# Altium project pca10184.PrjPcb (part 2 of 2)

## Sheet pca10184_connectors.SchDoc: =ProductName + ' - Connectors'
size A3; Organization: Nordic Semiconductor; DocumentNumber: 8; Revision: 0.3.4; SheetNumber: 8; SheetTotal: 9; Author: GETR; CompanyName: Nordic Semiconductor; DrawnBy: GETR; DocumentSize: A3
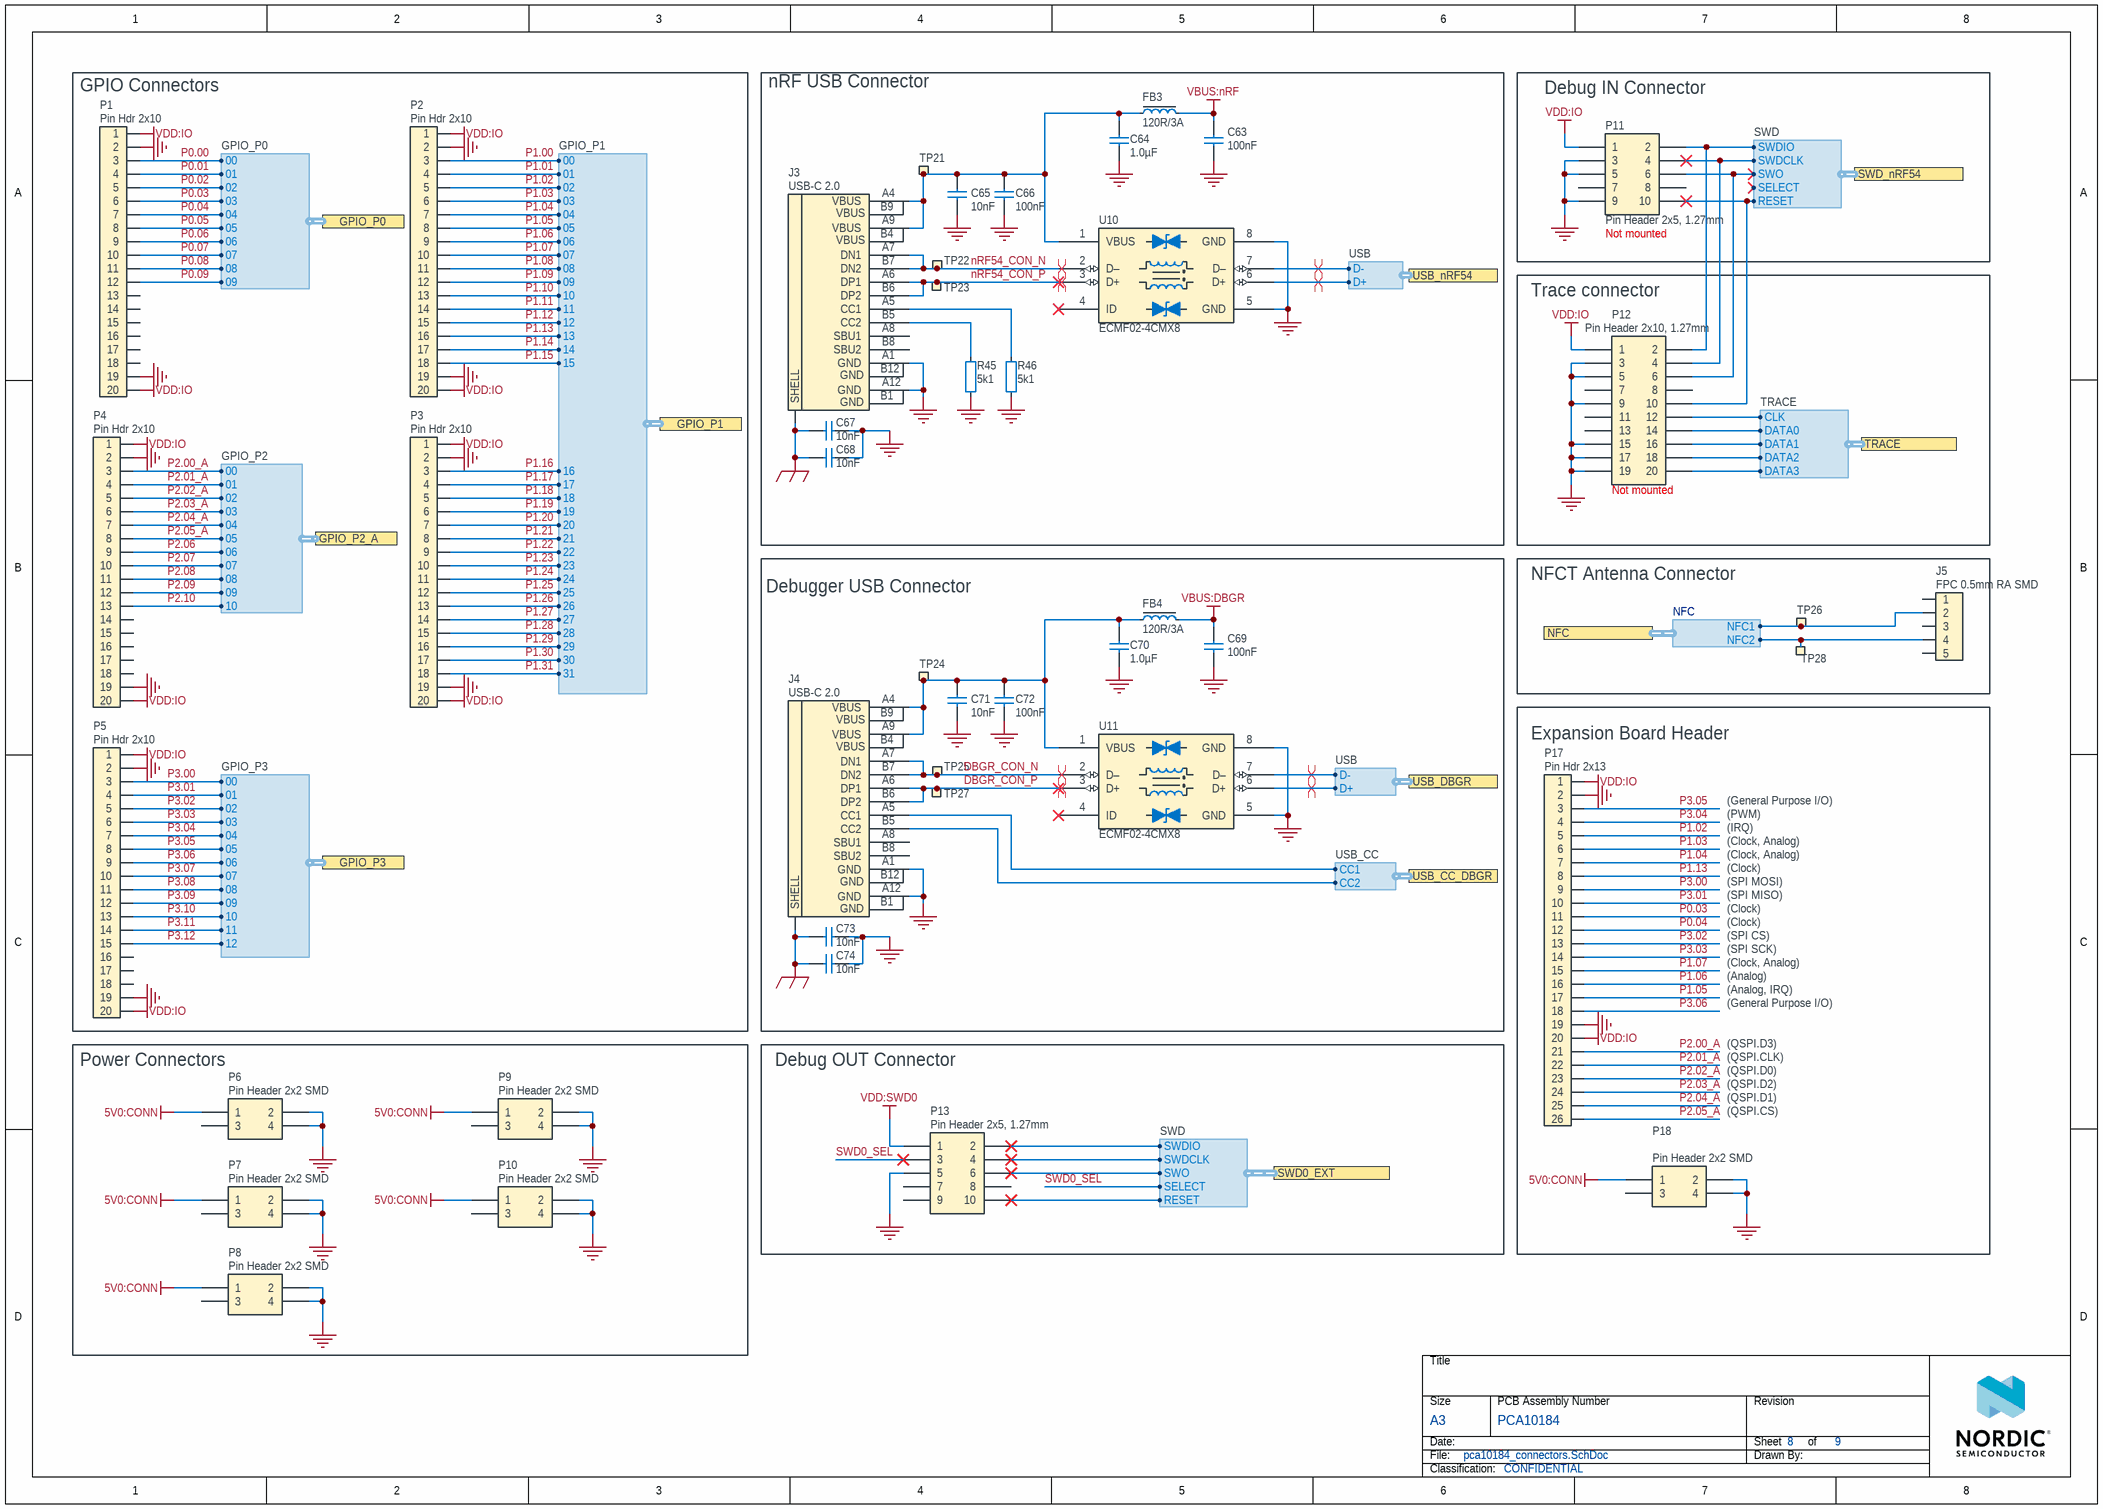
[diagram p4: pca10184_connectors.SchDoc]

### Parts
C63  100nF  [CAPC0603X03L_C]
C64  1.0µF  [CAPC1005X04L]
C65  10nF  [CAPC0603X03L_C]
C66  100nF  [CAPC0603X03L_C]
C67  10nF  [CAPC1005X04L]
C68  10nF  [CAPC1005X04L]
C69  100nF  [CAPC0603X03L_C]
C70  1.0µF  [CAPC1005X04L]
C71  10nF  [CAPC0603X03L_C]
C72  100nF  [CAPC0603X03L_C]
C73  10nF  [CAPC1005X04L]
C74  10nF  [CAPC1005X04L]
FB3  120R/3A  [INDC1608X06L]
FB4  120R/3A  [INDC1608X06L]
J3  USB-C 2.0  [SD-80259-001]
J4  USB-C 2.0  [SD-80259-001]
J5  FPC 0.5mm RA SMD  [FPC_05P-0.5mm-RA-SMD]
P1  Pin Hdr 2x10  [HDR_2x10-SMD]
P2  Pin Hdr 2x10  [HDR_2x10-SMD]
P3  Pin Hdr 2x10  [HDR_2x10-SMD]
P4  Pin Hdr 2x10  [HDR_2x10-SMD]
P5  Pin Hdr 2x10  [HDR_2x10-SMD]
P6  Pin Header 2x2 SMD  [HDR_2x2-SMD]
P7  Pin Header 2x2 SMD  [HDR_2x2-SMD]
P8  Pin Header 2x2 SMD  [HDR_2x2-SMD]
P9  Pin Header 2x2 SMD  [HDR_2x2-SMD]
P10  Pin Header 2x2 SMD  [HDR_2x2-SMD]
P11  Pin Header 2x5, 1.27mm  Assembly: Not mounted  [HDR_2x5-SMD-1.27mm-K]
P12  Pin Header 2x10, 1.27mm  Assembly: Not mounted  [HDR_2x10-SMD-1.27mm-NC]
P13  Pin Header 2x5, 1.27mm  [HDR_2x5-SMD-1.27mm-K]
P17  Pin Hdr 2x13  [HDR_2x13-SMD]
P18  Pin Header 2x2 SMD  [HDR_2x2-SMD]
R45  5k1  [RESC0603X03L_C]
R46  5k1  [RESC0603X03L_C]
TP21  Ø1.5mm,SMD  [TP_SMD_D1.5mm]  (value not drawn)  (no BOM)
TP22  Ø1.5mm,SMD  [TP_SMD_D1.5mm]  (value not drawn)  (no BOM)
TP23  Ø1.5mm,SMD  [TP_SMD_D1.5mm]  (value not drawn)  (no BOM)
TP24  Ø1.5mm,SMD  [TP_SMD_D1.5mm]  (value not drawn)  (no BOM)
TP25  Ø1.5mm,SMD  [TP_SMD_D1.5mm]  (value not drawn)  (no BOM)
TP26  Ø1.5mm,SMD  [TP_SMD_D1.5mm]  (value not drawn)  (no BOM)
TP27  Ø1.5mm,SMD  [TP_SMD_D1.5mm]  (value not drawn)  (no BOM)
TP28  Ø1.5mm,SMD  [TP_SMD_D1.5mm]  (value not drawn)  (no BOM)
U10  ECMF02-4CMX8  [UFDFN50P120X250X55-8N]
U11  ECMF02-4CMX8  [UFDFN50P120X250X55-8N]

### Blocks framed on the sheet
GPIO Connectors: P1-P5
nRF USB Connector: C63-C68 FB3 J3 R45 R46 TP21-TP23 U10
Debug IN Connector: P11
Trace connector: P12
Debugger USB Connector: C69-C74 FB4 J4 TP24 TP25 TP27 U11
NFCT Antenna Connector: J5 TP26 TP28
Expansion Board Header: P17 P18
Power Connectors: P6-P10
Debug OUT Connector: P13

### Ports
GPIO_P0 (harness GPIO_P0), GPIO_P1 (harness GPIO_P1), GPIO_P2_A (harness GPIO_P2), GPIO_P3 (harness GPIO_P3), NFC (harness NFC), SWD0_EXT (harness SWD), SWD_nRF54 (harness SWD), TRACE (harness TRACE), USB_CC_DBGR (harness USB_CC), USB_DBGR (harness USB), USB_nRF54 (harness USB)

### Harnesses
GPIO_P0: 00, 01, 02, 03, 04, 05, 06, 07, 08, 09
GPIO_P1: 00, 01, 02, 03, 04, 05, 06, 07, 08, 09, 10, 11, 12, 13, 14, 15, 16, 17, 18, 19, 20, 21, 22, 23, 24, 25, 26, 27, 28, 29, 30, 31
GPIO_P3: 00, 01, 02, 03, 04, 05, 06, 07, 08, 09, 10, 11, 12
SWD: SWDIO, SWDCLK, SWO, RESET, SELECT
USB: D+, D-
USB_CC: CC2, CC1
NFC: NFC2, NFC1
TRACE: CLK, DATA0, DATA1, DATA3, DATA2
GPIO_P2: 00, 01, 02, 03, 04, 05, 06, 07, 08, 09, 10

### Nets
5V0:CONN: P6.1 P7.1 P8.1 P9.1 P10.1 P18.1
GND: C63.1 C64.1 C65.1 C66.1 C67.2 C68.2 C69.1 C70.1 C71.1 C72.1 C73.2 C74.2 J3.A1(GND) J3.A12(GND) J4.A1(GND) J4.A12(GND) P1.2 P1.19 P2.2 P2.19 P3.2 P3.19 P4.2 P4.19 P5.2 P5.19 P6.2 P6.4 P7.2 P7.4 P8.2 P8.4 P9.2 P9.4 P10.2 P10.4 P11.3 P11.5 P11.9 P12.3 P12.5 P12.9 P12.15 P12.17 P12.19 P13.5 P17.2 P17.19 P18.2 P18.4 R45.1 R46.1 U10.5(GND) U10.8(GND) U11.5(GND) U11.8(GND)
Shield: C67.1 C68.1 C73.1 C74.1 J3.SHLD(SHELL) J4.SHLD(SHELL)
VBUS:DBGR: C69.2 FB4.2
VBUS:nRF: C63.2 FB3.2
VDD:IO: P1.1 P1.20 P2.1 P2.20 P3.1 P3.20 P4.1 P4.20 P5.1 P5.20 P11.1 P12.1 P17.1 P17.20
VDD:SWD0: P13.1
DBGR_CON_N: J4.A7(DN1) J4.B7(DN2) TP25.1 U11.2(D–)
DBGR_CON_P: J4.A6(DP1) J4.B6(DP2) TP27.1 U11.3(D+)
DBGR_N: U11.7(D–) ; port USB_DBGR.D-
DBGR_P: U11.6(D+) ; port USB_DBGR.D+
NFC1_N: J5.2 TP26.1 ; port NFC.NFC1
NFC2_P: J5.4 TP28.1 ; port NFC.NFC2
nRF54_CON_N: J3.A7(DN1) J3.B7(DN2) TP22.1 U10.2(D–)
nRF54_CON_P: J3.A6(DP1) J3.B6(DP2) TP23.1 U10.3(D+)
nRF54_RESET: P11.10 P12.10 ; port SWD_nRF54.RESET
P0.00: P1.3 ; port GPIO_P0.00
P0.01: P1.4 ; port GPIO_P0.01
P0.02: P1.5 ; port GPIO_P0.02
P0.03: P1.6 P17.11 ; port GPIO_P0.03
P0.04: P1.7 P17.12 ; port GPIO_P0.04
P0.05: P1.8 ; port GPIO_P0.05
P0.06: P1.9 ; port GPIO_P0.06
P0.07: P1.10 ; port GPIO_P0.07
P0.08: P1.11 ; port GPIO_P0.08
P0.09: P1.12 ; port GPIO_P0.09
P1.00: P2.3 ; port GPIO_P1.00
P1.01: P2.4 ; port GPIO_P1.01
P1.02: P2.5 P17.5 ; port GPIO_P1.02
P1.03: P2.6 P17.6 ; port GPIO_P1.03
P1.04: P2.7 P17.7 ; port GPIO_P1.04
P1.05: P2.8 P17.17 ; port GPIO_P1.05
P1.06: P2.9 P17.16 ; port GPIO_P1.06
P1.07: P2.10 P17.15 ; port GPIO_P1.07
P1.08: P2.11 ; port GPIO_P1.08
P1.09: P2.12 ; port GPIO_P1.09
P1.10: P2.13 ; port GPIO_P1.10
P1.11: P2.14 ; port GPIO_P1.11
P1.12: P2.15 ; port GPIO_P1.12
P1.13: P2.16 P17.8 ; port GPIO_P1.13
P1.14: P2.17 ; port GPIO_P1.14
P1.15: P2.18 ; port GPIO_P1.15
P1.16: P3.3 ; port GPIO_P1.16
P1.17: P3.4 ; port GPIO_P1.17
P1.18: P3.5 ; port GPIO_P1.18
P1.19: P3.6 ; port GPIO_P1.19
P1.20: P3.7 ; port GPIO_P1.20
P1.21: P3.8 ; port GPIO_P1.21
P1.22: P3.9 ; port GPIO_P1.22
P1.23: P3.10 ; port GPIO_P1.23
P1.24: P3.11 ; port GPIO_P1.24
P1.25: P3.12 ; port GPIO_P1.25
P1.26: P3.13 ; port GPIO_P1.26
P1.27: P3.14 ; port GPIO_P1.27
P1.28: P3.15 ; port GPIO_P1.28
P1.29: P3.16 ; port GPIO_P1.29
P1.30: P3.17 ; port GPIO_P1.30
P1.31: P3.18 ; port GPIO_P1.31
P2.00_A: P4.3 P17.21 ; port GPIO_P2_A.00
P2.01_A: P4.4 P17.22 ; port GPIO_P2_A.01
P2.02_A: P4.5 P17.23 ; port GPIO_P2_A.02
P2.03_A: P4.6 P17.24 ; port GPIO_P2_A.03
P2.04_A: P4.7 P17.25 ; port GPIO_P2_A.04
P2.05_A: P4.8 P17.26 ; port GPIO_P2_A.05
P2.06: P4.9 P12.12 ; port TRACE.CLK, port GPIO_P2_A.06
P2.07: P4.10 P11.6 P12.6 P12.14 ; port SWD_nRF54.SWO, port TRACE.DATA0, port GPIO_P2_A.07
P2.08: P4.11 P12.16 ; port TRACE.DATA1, port GPIO_P2_A.08
P2.09: P4.12 P12.18 ; port TRACE.DATA2, port GPIO_P2_A.09
P2.10: P4.13 P12.20 ; port TRACE.DATA3, port GPIO_P2_A.10
P3.00: P5.3 P17.9 ; port GPIO_P3.00
P3.01: P5.4 P17.10 ; port GPIO_P3.01
P3.02: P5.5 P17.13 ; port GPIO_P3.02
P3.03: P5.6 P17.14 ; port GPIO_P3.03
P3.04: P5.7 P17.4 ; port GPIO_P3.04
P3.05: P5.8 P17.3 ; port GPIO_P3.05
P3.06: P5.9 P17.18 ; port GPIO_P3.06
P3.07: P5.10 ; port GPIO_P3.07
P3.08: P5.11 ; port GPIO_P3.08
P3.09: P5.12 ; port GPIO_P3.09
P3.10: P5.13 ; port GPIO_P3.10
P3.11: P5.14 ; port GPIO_P3.11
P3.12: P5.15 ; port GPIO_P3.12
SWD0_CLK_EXT: P13.6 ; port SWD0_EXT.SWO
SWD0_IO_EXT: P13.10 ; port SWD0_EXT.RESET
SWD0_RESET_EXT: P13.2 ; port SWD0_EXT.SWDIO
SWD0_SEL: P13.3 ; port SWD0_EXT.SELECT
SWD0_SWO_EXT: P13.4 ; port SWD0_EXT.SWDCLK
SWDCLK: P11.4 P12.4 ; port SWD_nRF54.SWDCLK
SWDIO: P11.2 P12.2 ; port SWD_nRF54.SWDIO
USB_nRF54_D+: U10.6(D+) ; port USB_nRF54.D+
USB_nRF54_D-: U10.7(D–) ; port USB_nRF54.D-
NetC64_2: C64.2 C65.2 C66.2 FB3.1 J3.A4(VBUS) J3.A9(VBUS) TP21.1 U10.1(VBUS)
NetC70_2: C70.2 C71.2 C72.2 FB4.1 J4.A4(VBUS) J4.A9(VBUS) TP24.1 U11.1(VBUS)
NetJ3_A5: J3.A5(CC1) R46.2
NetJ3_B5: J3.B5(CC2) R45.2
NetJ4_A5: J4.A5(CC1) ; port USB_CC_DBGR.CC1
NetJ4_B5: J4.B5(CC2) ; port USB_CC_DBGR.CC2

Not connected (* = marked no-connect by the designer): J3 A8(SBU1) B8(SBU2); J4 A8(SBU1) B8(SBU2); J5 1 3 5; P1 13 14 15 16 17 18; P4 14 15 16 17 18; P5 16 17 18; P6 3; P7 3; P8 3; P9 3; P10 3; P11 7 8; P12 7 8 11 13; P13 7 8 9; P18 3; U10 4(ID)*; U11 4(ID)*

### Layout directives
differential pair; differential pair class nRF54; net class USB: DBGR_CON_N, DBGR_CON_P, nRF54_CON_N, nRF54_CON_P
differential pair; differential pair class IMCU; net class USB: DBGR_N, DBGR_P, USB_nRF54_D+, USB_nRF54_D-

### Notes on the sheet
- (Clock, Analog)
- (IRQ)
- (PWM)
- (General Purpose I/O)
- (Clock)
- (SPI MOSI)
- (SPI MISO)
- (Analog)
- (Analog, IRQ)
- (SPI SCK)
- (SPI CS)
- (QSPI.D3)
- (QSPI.D2)
- (QSPI.D0)
- (QSPI.D1)
- (QSPI.CS)
- (QSPI.CLK)

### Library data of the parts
C63 C66 C69 C72 = C0201-100n: Capacitor, X5R, ±10%, 100nF, 16V; Manufacturer: N.A.; Part number IPS: 00000001248, 00000002505; Part number Norautron: 262071862; Part number NEMS: 100200078; Pad Count: 2; Component Status: Active
C64 C70 = C0402-1µ0-16V-X5R: Capacitor, Ceramic, X5R, ±10%, 16V; Manufacturer: Murata; Manufacturer Part Number: GRT155R61C105KE01D; Part number NEMS: 100200452; Artikkelnr Noca: N.A.; Pad Count: 2; Component Status: Active
C65 C71 = C0201-10n: Capacitor, X7R, ±10%, 10nF, 10V; Manufacturer: N.A.; Part number IPS: 00000003480; Part number Norautron: 26621779; Part number NEMS: 100200067; Pad Count: 2; Component Status: Active
C67 C68 C73 C74 = C0402-10n: Capacitor, X7R, ±10%; Manufacturer: N.A.; Part number IPS: 00000007784; Part number NEMS: 100200173; Component Status: Active; Pad Count: 2; Note: 16V; Artikkelnr Noca: 20039166
FB3 FB4 = FB0603-120R@100MHz-3000mA: Ferrite Bead, 120 Ohm @ 100MHz, 3000mA, 30 mOhm Max; Manufacturer: Murata; Manufacturer Part Number: BLM18KG121TN1D; Part number NEMS: 100300103; Component Status: Active; Pad Count: 2; Note: Chip EMIFIL Inductor Type Chip Ferrite Bead; Artikkelnr Noca: N.A.
J3 J4 = 80259-1021: USB-C Receptacle, 16 Pin, USB 2.0; Manufacturer: Bellweather Electronic Corp.; Part number NEMS: 100500830; Component Status: Active; Pad Count: 16; Note: N.A.; System: Connector
J5 = FPC_05P-0.5mm-RA-SMD: 0.5mm FPC, 5P,Right Angle SMT,Double Contact,H=1.2mm,White, Tin plated; Manufacturer: WCON; Manufacturer Part Number: 5141-05RZDNWR03; Part number NEMS: 100500528; Note: (Replaced 5141-05RZDNWR02); Artikkelnr Noca: N.A.; Pad Count: 7; Component Status: Active; System: Connector
P1-P5 = Pin Header 2x10 SMD, 2.54mm: Pin Header 2x10, 2.54mm (100mil) SMD; Manufacturer: WCON; Manufacturer Part Number: 1125-1210S0M116CR09; Part number NEMS: 100500738; Pad Count: 20; Artikkelnr Noca: N.A.; Component Status: Active; System: Connector
P6-P10 P18 = Pin Header 2x2 SMD: Pin Header 2x2, SMD, 2.54mm (100mil); Manufacturer: WCON; Manufacturer Part Number: 1125-1202S0M116CR03; Part number NEMS: 100500770; Component Status: Active; Pad Count: 4; Note: N.A.; System: Connector
P11 P13 = Pin Header 2x5 SMD, 1.27mm, KS: Pin Header 2x5, 1.27mm (50mil), SMD, Keying Shroud; Manufacturer: WCON; Manufacturer Part Number: 3132-10MS0BK00R5; Part number NEMS: 100500261; Note: (Replaced 3132-10MS0BK00R1); Artikkelnr Noca: N.A.; Pad Count: 10; Component Status: Active; System: Connector
P12 = Pin Header 2x10 SMD, 1.27mm, KS, N.C.: Pin Header 2x10, 1.27mm (50mil), SMD, Keying Shroud; Manufacturer: WCON; Manufacturer Part Number: 3132-20MS0BK00R1; Part number NEMS: 100500279; Note: N.A.; Pad Count: 20; Component Status: Active; System: Connector
P17 = Pin Header 2x13 SMD, 2.54mm: Pin Header 2x13, 2.54mm (100mil) SMD; Manufacturer: WCON; Manufacturer Part Number: 1125-1213S0M116CR09; Part number NEMS: 100500908; Component Status: Active; Pad Count: 26; Artikkelnr Noca: N.A.; System: Connector
R45 R46 = R0201-5k1: Resistor, ±1%, 0.05W; Manufacturer: N.A.; Part number Norautron: 26192285; Part number NEMS: 100100565; Pad Count: 2; Note: Chip Res 1%; Component Status: Active
TP21-TP28 = TP_SMD_Ø1.5MM: 1.5mm circular SMD testpad; Manufacturer: Nordic Semiconductor; Manufacturer Part Number: N.A.; Part number NEMS: 100500477; Pad Count: 1; Component Status: Active
U10 U11 = ECMF02-4CMX8: 2 Line Common mode filter with ESD protection for USB 2.0 interface, DCRmax = 4Ohm, -40°C ~ 125°C; Manufacturer: STMicroelectronics; Part number NEMS: 100800034; Component Status: Active; Pad Count: 8; Note: N.A.

## Sheet pca10184_mechanical.SchDoc: =ProductName + ' - Mechanical'
size A4; Organization: Nordic Semiconductor; DocumentNumber: 9; Revision: 0.3.4; SheetNumber: 9; SheetTotal: 9; Author: GETR; CompanyName: Nordic Semiconductor; DrawnBy: GETR; DocumentSize: A4
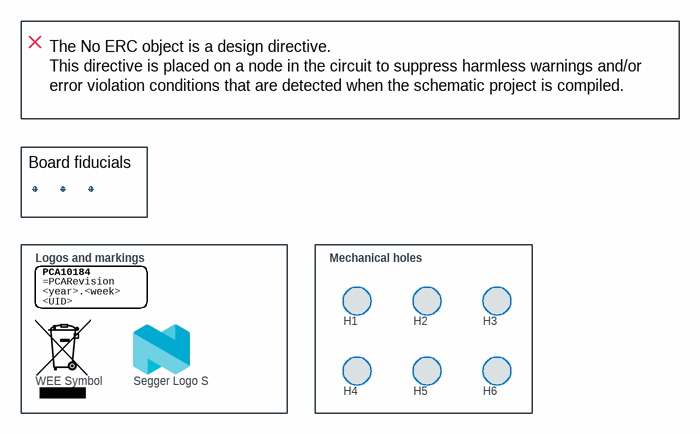
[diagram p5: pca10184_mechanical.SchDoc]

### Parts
Fid1  Fiducial mark  [Fiducial]  (value not drawn)
Fid2  Fiducial mark  [Fiducial]  (value not drawn)
Fid3  Fiducial mark  [Fiducial]  (value not drawn)
H1  MountingHole_NPTH  [MountingHole_3.2_M3]  (value not drawn)  (no BOM)
H2  MountingHole_NPTH  [MountingHole_3.2_M3]  (value not drawn)  (no BOM)
H3  MountingHole_NPTH  [MountingHole_3.2_M3]  (value not drawn)  (no BOM)
H4  MountingHole_NPTH  [MountingHole_3.2_M3]  (value not drawn)  (no BOM)
H5  MountingHole_NPTH  [MountingHole_3.2_M3]  (value not drawn)  (no BOM)
H6  MountingHole_NPTH  [MountingHole_3.2_M3]  (value not drawn)  (no BOM)
LABEL1  12x12mm  [LabelSilk_12x12]  (value not drawn)
LOGO1  WEE Symbol  [WEE_3x4.5mm]  (no BOM)
LOGO3  Segger Logo S  [SEGGER_LOGO_S]  (no BOM)

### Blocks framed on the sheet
Logos and markings: LABEL1 LOGO1 LOGO3
Mechanical holes: H1-H6

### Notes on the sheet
- The No ERC object is a design directive.
  This directive is placed on a node in the circuit to suppress harmless warnings and/or error violation conditions that are detected when the schematic project is compiled.
- Board fiducials

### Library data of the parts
Fid1-Fid3 = Fid-Mark: Manufacturer: N.A.; Part number NEMS: 100500073; Value: N.A.; Pad Count: 1; Component Status: Active; System: Connector
H1-H6 = MountingHole_3.2_M3: Mounting hole, 3.2mm, M3, no annular; Manufacturer: N.A.; Part number NEMS: 101200008; Rule: UNIONINDEX=0¦RULEKIND=Clearance¦NETSCOPE=DifferentNets¦LAYERKIND=SameLayer¦NAME=Schematic Clearance Constraint¦GAP=10mil¦GENERICCLEARANCE=10mil¦IGNOREPADTOPADCLEARANCEINFOOTPRINT=TRUE¦OBJECTCLEARANCES=ClearanceObj_Arc-ClearanceObj_Hole:0;ClearanceObj_Track-ClearanceObj_Hole:0;ClearanceObj_SMDPad-ClearanceObj_Hole:0;ClearanceObj_THPad-ClearanceObj_Hole:0;ClearanceObj_Via-ClearanceObj_Hole:0;ClearanceObj_Fill-ClearanceObj_Hole:0;ClearanceObj_Poly-ClearanceObj_Hole:0;ClearanceObj_Region-ClearanceObj_Hole:0;ClearanceObj_Text-ClearanceObj_Hole:0¦UNIT=Metric; Rule: UNIONINDEX=0¦RULEKIND=RoutingVias¦NETSCOPE=AnyNet¦LAYERKIND=SameLayer¦NAME=Schematic Routing Via Style¦HOLEWIDTH=0mil¦WIDTH=0mil¦VIASTYLE=Through Hole¦MINHOLEWIDTH=0mil¦MINWIDTH=0mil¦MAXHOLEWIDTH=78.7402mil¦MAXWIDTH=78.7402mil¦UNIT=Metric; Component Status: Active; Pad Count: 0
LABEL1 = Label_12x12: PCA version label, stick-on, 12x12mm; Manufacturer: Ellco Etikett; Manufacturer Part Number: A33512‐01; Part number NEMS: 101200028; Component Status: Active; Pad Count: 0; Note: N.A.
LOGO1 = WEEE Symbol 3x4.5mm: WEEE Directive symbol; Manufacturer: N.A.; Part number NEMS: 101100006; Component Status: Active; Pad Count: 0
LOGO3 = Segger Logo S: Segger logo, small size; Manufacturer: N.A.; Part number NEMS: 101100004; Component Status: Active; Pad Count: 0

## Sheet pca10184_misc.SchDoc: =ProductName + ' - Misc'
size A3; Author: GETR; CompanyName: Nordic Semiconductor; DrawnBy: GETR; DocumentNumber: 5; Revision: 0.3.4; SheetNumber: 5; SheetTotal: 9
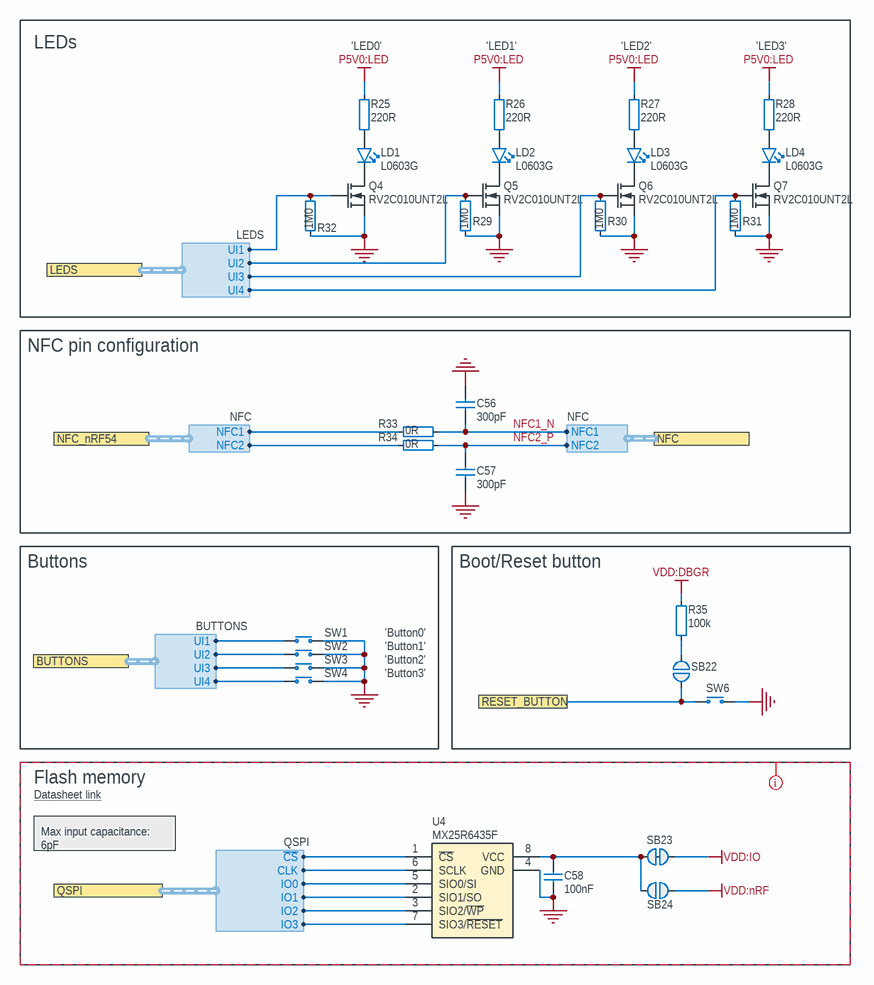
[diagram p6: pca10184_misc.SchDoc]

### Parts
C56  300pF  [CAPC1005X04L]
C57  300pF  [CAPC1005X04L]
C58  100nF  [CAPC0603X03L_C]
LD1  L0603G  [LED_0603_G]
LD2  L0603G  [LED_0603_G]
LD3  L0603G  [LED_0603_G]
LD4  L0603G  [LED_0603_G]
Q4  RV2C010UNT2L  [DFN65P100X40-3L]
Q5  RV2C010UNT2L  [DFN65P100X40-3L]
Q6  RV2C010UNT2L  [DFN65P100X40-3L]
Q7  RV2C010UNT2L  [DFN65P100X40-3L]
R25  220R  [RESC0603X03L_C]
R26  220R  [RESC0603X03L_C]
R27  220R  [RESC0603X03L_C]
R28  220R  [RESC0603X03L_C]
R29  1M0  [RESC0603X03L_C]
R30  1M0  [RESC0603X03L_C]
R31  1M0  [RESC0603X03L_C]
R32  1M0  [RESC0603X03L_C]
R33  0R  [RESC1005X04L]
R34  0R  [RESC1005X04L]
R35  100k  [RESC0603X03L_C]
SB22  Solderbridge  [Solderbridge]  (value not drawn)  (no BOM)
SB23  Solderbridge  [Solderbridge_Shorted]  (value not drawn)  (net tie, no BOM)
SB24  Solderbridge  [Solderbridge]  (value not drawn)  (no BOM)
SW1  PB SW  [Switch-PB-6.2x6.3mm-SMD]  (value not drawn)
SW2  PB SW  [Switch-PB-6.2x6.3mm-SMD]  (value not drawn)
SW3  PB SW  [Switch-PB-6.2x6.3mm-SMD]  (value not drawn)
SW4  PB SW  [Switch-PB-6.2x6.3mm-SMD]  (value not drawn)
SW6  PB SW  [Switch-PB-6.2x6.3mm-SMD]  (value not drawn)
U4  MX25R6435F  [SON127P600X80_HS-9N]

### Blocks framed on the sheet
LEDs: LD1-LD4 Q4-Q7 R25-R32
NFC pin configuration: C56 C57 R33 R34
Buttons: SW1-SW4
Boot/Reset button: R35 SB22 SW6
Flash memory: C58 SB23 SB24 U4

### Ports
BUTTONS (harness BUTTONS), LEDS (harness LEDS), NFC (harness NFC), NFC_nRF54 (harness NFC), QSPI (harness QSPI), RESET_BUTTON

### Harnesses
NFC: NFC2, NFC1
LEDS: UI2, UI1, UI3, UI4
QSPI: ~{CS}, IO0, CLK, IO1, IO2, IO3
BUTTONS: UI2, UI3, UI4, UI1

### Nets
GND: C56.2 C57.1 C58.2 Q4.2(S) Q5.2(S) Q6.2(S) Q7.2(S) R29.2 R30.2 R31.2 R32.2 SW1.1(N.O) SW2.1(N.O) SW3.1(N.O) SW4.1(N.O) SW6.1(N.O) U4.4(GND) U4.9(GND)
P5V0:LED: R25.2 R26.2 R27.2 R28.2
VDD:DBGR: R35.2
VDD:IO: SB23.1
VDD:nRF: SB24.1
NFC1_N: C56.1 R33.2 ; port NFC.NFC1
NFC2_P: C57.2 R34.2 ; port NFC.NFC2
NFC_N: R33.1 ; port NFC_nRF54.NFC1
NFC_P: R34.1 ; port NFC_nRF54.NFC2
P0.05: SW4.2(COM) ; port BUTTONS.UI4
P1.08: SW3.2(COM) ; port BUTTONS.UI3
P1.09: SW2.2(COM) ; port BUTTONS.UI2
P1.22: Q4.1(G) R32.1 ; port LEDS.UI1
P1.25: Q5.1(G) R29.1 ; port LEDS.UI2
P1.26: SW1.2(COM) ; port BUTTONS.UI1
P1.27: Q6.1(G) R30.1 ; port LEDS.UI3
P1.28: Q7.1(G) R31.1 ; port LEDS.UI4
P2.00_B: U4.7(SIO3/~{RESET}) ; port QSPI.IO3
P2.01_B: U4.6(SCLK) ; port QSPI.CLK
P2.02_B: U4.5(SIO0/SI) ; port QSPI.IO0
P2.03_B: U4.3(SIO2/~{WP}) ; port QSPI.IO2
P2.04_B: U4.2(SIO1/SO) ; port QSPI.IO1
P2.05_B: U4.1(~{CS}) ; port QSPI.~{CS}
NetC58_1: C58.1 SB23.2 SB24.2 U4.8(VCC)
NetLD1_1: LD1.1(C) Q4.3(D)
NetLD1_2: LD1.2(A) R25.1
NetLD2_1: LD2.1(C) Q5.3(D)
NetLD2_2: LD2.2(A) R26.1
NetLD3_1: LD3.1(C) Q6.3(D)
NetLD3_2: LD3.2(A) R27.1
NetLD4_1: LD4.1(C) Q7.3(D)
NetLD4_2: LD4.2(A) R28.1
NetR35_1: R35.1 SB22.2
NetSB22_1: SB22.1 SW6.2(COM) ; port RESET_BUTTON

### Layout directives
CompClassName: Flash: GND, VDD:IO, VDD:nRF

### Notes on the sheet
- (near R25) 'LED0'
- (near R26) 'LED1'
- (near R27) 'LED2'
- (near R28) 'LED3'
- 'Button1'
- 'Button2'
- 'Button3'
- 'Button0'
- Datasheet link <https://www.mxic.com.tw/Lists/Datasheet/Attachments/8868/MX25R6435F,%20Wide%20Range,%2064Mb,%20v1.6.pdf>
- Max input capacitance: 6pF

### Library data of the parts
C56 C57 = C0402-300p: Capacitor, C0G, ±5%, 50V; Manufacturer: N.A.; Part number IPS: 00000007788; Part number NEMS: 100200155; Artikkelnr Noca: 20020004; Pad Count: 2; Component Status: Active
C58 = C0201-100n: as C63 on sheet pca10184_connectors
LD1-LD4 = VS 25C7M5: LED, Green, 0603, 573nm, Vf=2.0V, 24mcd, - 40 to +85°C; Manufacturer: Victory Electronics; Part number IPS: 00000001274, 00000009961; Part number Norautron: 26313411; Part number NEMS: 101400097; Pad Count: 2; Note: N.A.; Artikkelnr Noca: 13019193; Component Status: Active
Q4-Q7 = RV2C010UNT2L: N-Channel MOSFET, 20V, 1A, 470mOhm, 400mW, -55°C ~ 150°C; Manufacturer: Rohm Semiconductor; Part number IPS: 00000009976; Part number Norautron: 26320026; Part number NEMS: 101300132; Note: N.A.; Artikkelnr Noca: 35010020; Pad Count: 3; Component Status: Active
R25-R28 = R0201-220: Resistor, ±1%, 0.05W; Manufacturer: N.A.; Part number IPS: 00000000863; Part number Norautron: 26107014; Part number NEMS: 100100032; Note: Chip Res 1%; Pad Count: 2; Component Status: Active
R29-R32 = R0201-1M0: Resistor, ±1%, 0.05W; Manufacturer: N.A.; Part number IPS: 00000001418; Part number Norautron: 26107108; Part number NEMS: 100100093; Component Status: Active; Pad Count: 2; Note: Chip Res 1%
R33 R34 = R0402-0R: Resistor, ±5%, 0.063W; Manufacturer: N.A.; Part number IPS: 00000007128; Part number NEMS: 100100109; Component Status: Active; Pad Count: 2; Note: Chip Res 5%; Artikkelnr Noca: 27049000
R35 = R0201-100k: Resistor, ±1%, 0.05W; Manufacturer: N.A.; Part number IPS: 00000001419; Part number Norautron: 26108487; Part number NEMS: 100100080; Note: Chip Res 1%; Pad Count: 2; Component Status: Active
SB22 SB24 = Solderbridge: Manufacturer: N.A.; Part number NEMS: 100500458; Pad Count: 2; Component Status: Active; System: Connector
SB23 = Solderbridge Shorted: Shorted Solderbridge; Manufacturer: N.A.; Part number NEMS: 100500459; Pad Count: 2; Component Status: Active; System: Connector
SW1-SW4 SW6 = Switch-PB-6.2x6.3mm-SMD: Tactile Switch, SPNO, SMD, 160gf, 6.2x6.3x2.5mm; Manufacturer: Dailywell; Manufacturer Part Number: TS604VM1-025BR-R; Part number IPS: 00000007812; Part number NEMS: 101500001, 101500133; Note: N.A.; Artikkelnr Noca: 50019106; Pad Count: 4; Component Status: Active
U4 = MX25R6435FZNIL0: Ultra low power, 64M-bit, serial multi I/O flash memory; Manufacturer: Macronix; Part number IPS: 00000004370; Part number NEMS: 101900438; Note: N.A.; Artikkelnr Noca: 15020015; Pad Count: 8; Component Status: Active

## Sheet pca10184_level_shifters.SchDoc: =ProductName + ' - Level Shifters'
size A3; Organization: Nordic Semiconductor; DocumentNumber: 4; Revision: 0.3.4; SheetNumber: 4; SheetTotal: 9; Author: GETR; CompanyName: Nordic Semiconductor; DrawnBy: GETR; DocumentSize: A4
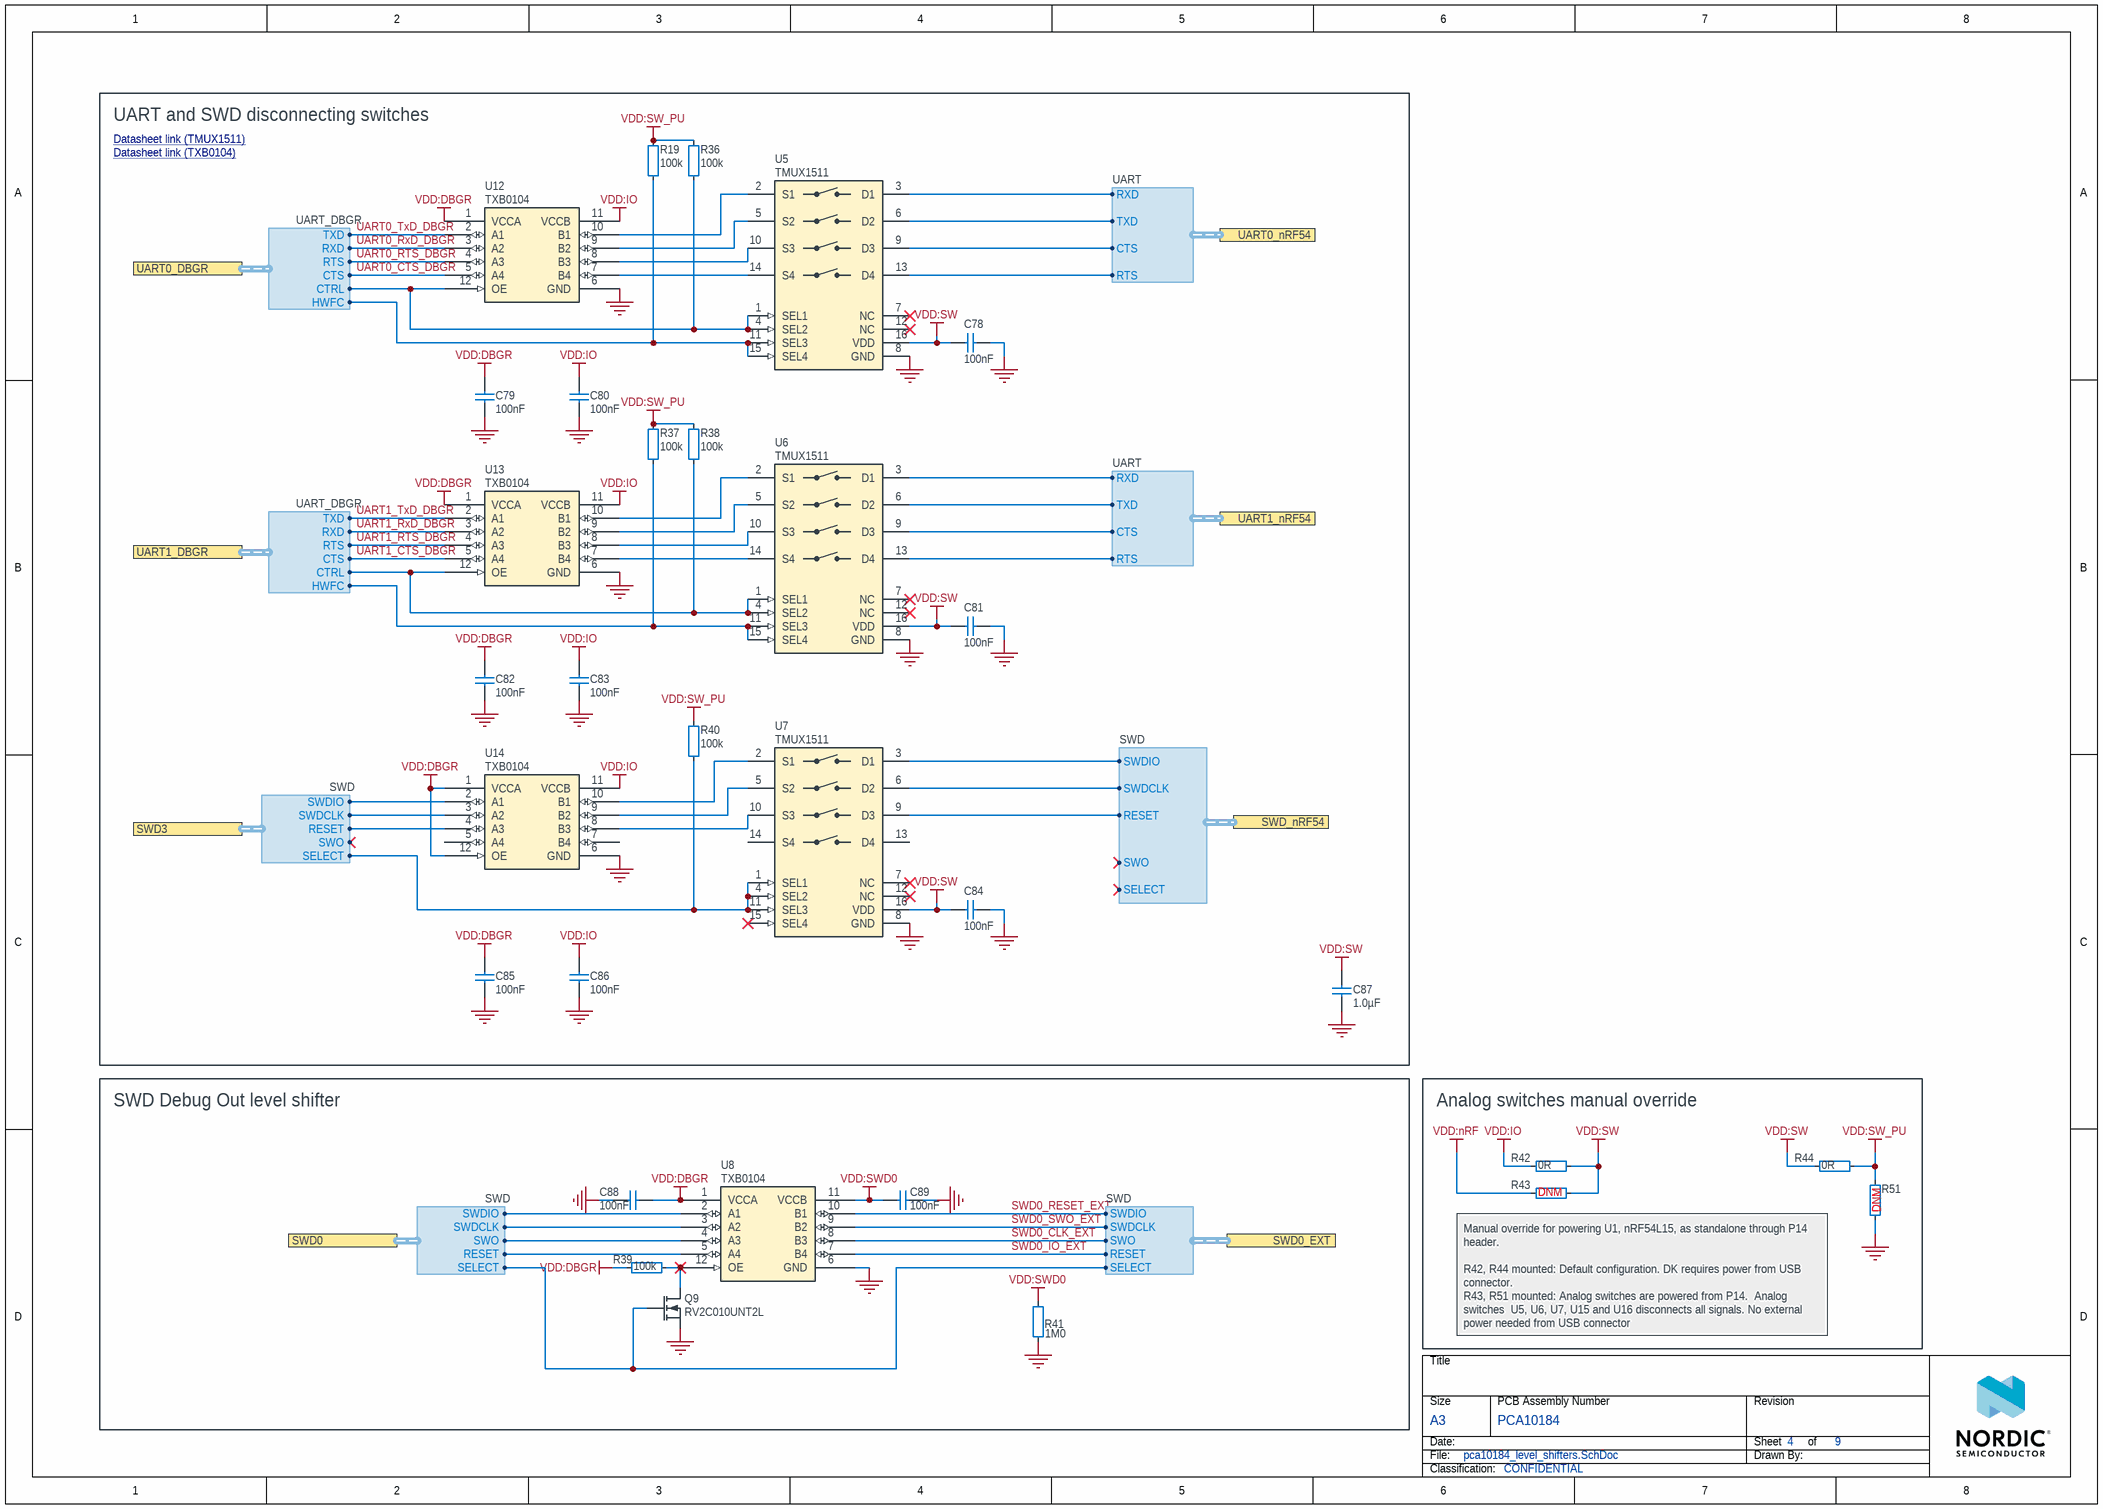
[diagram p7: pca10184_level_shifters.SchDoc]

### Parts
C78  100nF  [CAPC0603X03L_C]
C79  100nF  [CAPC0603X03L_C]
C80  100nF  [CAPC0603X03L_C]
C81  100nF  [CAPC0603X03L_C]
C82  100nF  [CAPC0603X03L_C]
C83  100nF  [CAPC0603X03L_C]
C84  100nF  [CAPC0603X03L_C]
C85  100nF  [CAPC0603X03L_C]
C86  100nF  [CAPC0603X03L_C]
C87  1.0µF  [CAPC1005X04L]
C88  100nF  [CAPC0603X03L_C]
C89  100nF  [CAPC0603X03L_C]
Q9  RV2C010UNT2L  [DFN65P100X40-3L]
R19  100k  [RESC0603X03L_C]
R36  100k  [RESC0603X03L_C]
R37  100k  [RESC0603X03L_C]
R38  100k  [RESC0603X03L_C]
R39  100k  [RESC0603X03L_C]
R40  100k  [RESC0603X03L_C]
R41  1M0  [RESC0603X03L_C]
R42  0R  [RESC1005X04L]
R43  DNM  [RESC1005X04L]
R44  0R  [RESC1005X04L]
R51  DNM  [RESC1005X04L]
U5  TMUX1511  [XQFN40P180X260X50-16N]
U6  TMUX1511  [XQFN40P180X260X50-16N]
U7  TMUX1511  [XQFN40P180X260X50-16N]
U8  TXB0104  [QFN12P40_170X200X55L50X20]
U12  TXB0104  [QFN12P40_170X200X55L50X20]
U13  TXB0104  [QFN12P40_170X200X55L50X20]
U14  TXB0104  [QFN12P40_170X200X55L50X20]

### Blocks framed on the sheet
UART and SWD disconnecting switches: C78-C87 R19 R36-R38 R40 U5-U7 U12-U14
SWD Debug Out level shifter: C88 C89 Q9 R39 R41 U8
Analog switches manual override: R42-R44 R51

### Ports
SWD0 (harness SWD), SWD0_EXT (harness SWD), SWD3 (harness SWD), SWD_nRF54 (harness SWD), UART0_DBGR (harness UART_DBGR), UART0_nRF54 (harness UART), UART1_DBGR (harness UART_DBGR), UART1_nRF54 (harness UART)

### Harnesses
SWD: SWDIO, SWDCLK, SWO, RESET, SELECT
UART_DBGR: RTS, CTS, RXD, TXD, HWFC, CTRL
UART: RTS, CTS, RXD, TXD

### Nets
GND: C78.2 C79.2 C80.2 C81.2 C82.2 C83.2 C84.2 C85.2 C86.2 C87.1 C88.1 C89.2 Q9.2(S) R41.1 R51.2 U5.8(GND) U6.8(GND) U7.8(GND) U8.6(GND) U12.6(GND) U13.6(GND) U14.6(GND)
VDD:DBGR: C79.1 C82.1 C85.1 C88.2 R39.2 U8.1(VCCA) U12.1(VCCA) U13.1(VCCA) U14.1(VCCA) U14.12(OE)
VDD:IO: C80.1 C83.1 C86.1 R42.1 U12.11(VCCB) U13.11(VCCB) U14.11(VCCB)
VDD:nRF: R43.1
VDD:SW: C78.1 C81.1 C84.1 C87.2 R42.2 R43.2 R44.2 U5.16(VDD) U6.16(VDD) U7.16(VDD)
VDD:SW_PU: R19.1 R36.1 R37.1 R38.1 R40.1 R44.1 R51.1
VDD:SWD0: C89.1 R41.2 U8.11(VCCB)
nRF54_RESET: U7.9(D3) ; port SWD_nRF54.RESET
P0.06: U5.6(D2) ; port UART0_nRF54.TXD
P0.07: U5.3(D1) ; port UART0_nRF54.RXD
P0.08: U5.13(D4) ; port UART0_nRF54.RTS
P0.09: U5.9(D3) ; port UART0_nRF54.CTS
P1.16: U6.6(D2) ; port UART1_nRF54.TXD
P1.17: U6.3(D1) ; port UART1_nRF54.RXD
P1.18: U6.13(D4) ; port UART1_nRF54.RTS
P1.19: U6.9(D3) ; port UART1_nRF54.CTS
SWD0_CLK_EXT: U8.8(B3) ; port SWD0_EXT.SWO
SWD0_IO_EXT: U8.7(B4) ; port SWD0_EXT.RESET
SWD0_RESET_EXT: U8.10(B1) ; port SWD0_EXT.SWDIO
SWD0_SEL: Q9.1(G) ; port SWD0.SELECT, port SWD0_EXT.SELECT
SWD0_SWO_EXT: U8.9(B2) ; port SWD0_EXT.SWDCLK
SWD3_CTRL: R40.2 U7.1(SEL1) U7.4(SEL2) U7.11(SEL3) ; port SWD3.SELECT
SWDCLK: U7.6(D2) ; port SWD_nRF54.SWDCLK
SWDIO: U7.3(D1) ; port SWD_nRF54.SWDIO
UART0_CTRL: R36.2 U5.1(SEL1) U5.4(SEL2) U12.12(OE) ; port UART0_DBGR.CTRL
UART0_CTS_DBGR: U12.5(A4) ; port UART0_DBGR.CTS
UART0_HWFC: R19.2 U5.11(SEL3) U5.15(SEL4) ; port UART0_DBGR.HWFC
UART0_RTS_DBGR: U12.4(A3) ; port UART0_DBGR.RTS
UART0_RxD_DBGR: U12.3(A2) ; port UART0_DBGR.RXD
UART0_TxD_DBGR: U12.2(A1) ; port UART0_DBGR.TXD
UART1_CTRL: R38.2 U6.1(SEL1) U6.4(SEL2) U13.12(OE) ; port UART1_DBGR.CTRL
UART1_CTS_DBGR: U13.5(A4) ; port UART1_DBGR.CTS
UART1_HWFC: R37.2 U6.11(SEL3) U6.15(SEL4) ; port UART1_DBGR.HWFC
UART1_RTS_DBGR: U13.4(A3) ; port UART1_DBGR.RTS
UART1_RxD_DBGR: U13.3(A2) ; port UART1_DBGR.RXD
UART1_TxD_DBGR: U13.2(A1) ; port UART1_DBGR.TXD
NetQ9_3: Q9.3(D) R39.1 U8.12(OE)
NetR6_2: U8.2(A1) ; port SWD0.SWDIO
NetR12_2: U8.3(A2) ; port SWD0.SWDCLK
NetR13_2: U8.4(A3) ; port SWD0.SWO
NetR47_2: U8.5(A4) ; port SWD0.RESET
NetR48_2: U14.2(A1) ; port SWD3.SWDIO
NetR49_2: U14.3(A2) ; port SWD3.SWDCLK
NetR50_2: U14.4(A3) ; port SWD3.RESET
NetU5_2: U5.2(S1) U12.10(B1)
NetU5_5: U5.5(S2) U12.9(B2)
NetU5_10: U5.10(S3) U12.8(B3)
NetU5_14: U5.14(S4) U12.7(B4)
NetU6_2: U6.2(S1) U13.10(B1)
NetU6_5: U6.5(S2) U13.9(B2)
NetU6_10: U6.10(S3) U13.8(B3)
NetU6_14: U6.14(S4) U13.7(B4)
NetU7_2: U7.2(S1) U14.10(B1)
NetU7_5: U7.5(S2) U14.9(B2)
NetU7_10: U7.10(S3) U14.8(B3)

Not connected (* = marked no-connect by the designer): U5 7(NC)* 12(NC)*; U6 7(NC)* 12(NC)*; U7 7(NC)* 12(NC)* 13(D4) 14(S4) 15(SEL4)*; U14 5(A4) 7(B4)

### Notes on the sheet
- Datasheet link (TMUX1511) <https://www.ti.com/lit/ds/symlink/tmux1511.pdf?ts=1730882090102&ref_url=https%253A%252F%252Fwww.mouser.dk%252F>
- Datasheet link (TXB0104) <https://www.ti.com/lit/ds/symlink/txb0104.pdf?src-supplier=IHS+Markit>
- (near R43) Manual override for powering U1, nRF54L15, as standalone through P14 header.
  R42, R44 mounted: Default configuration. DK requires power from USB connector.
  R43, R51 mounted: Analog switches are powered from P14.  Analog switches  U5, U6, U7, U15 and U16 disconnects all signals. No external power needed from USB connector

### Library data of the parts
C78-C86 C88 C89 = C0201-100n: Capacitor, X5R, ±10%; Manufacturer: N.A.; Part number IPS: 00000001248, 00000002505; Part number Norautron: 262071862; Part number NEMS: 100200078; Pad Count: 2; Note: 16V; Component Status: Active
C87 = C0402-1µ0-6.3V-X5R-10%: Capacitor, X5R, ±10%, 6.3V; Manufacturer: N.A.; Part number Norautron: 26207137; Part number NEMS: 100200498; Pad Count: 2; Component Status: Active
Q9 = RV2C010UNT2L: as Q4-Q7 on sheet pca10184_misc
R19 R36-R40 = R0201-100k: as R35 on sheet pca10184_misc
R41 = R0201-1M0: as R29 on sheet pca10184_misc
R42 R44 = R0402-0R: as R33 on sheet pca10184_misc
R43 R51 = R0402-0R: Resistor, ±5%, 0.063W; Manufacturer: N.A.; Part number IPS: 00000007128; Part number NEMS: 100100109; Component Status: Active; Pad Count: 2; Value: 0R; Note: Chip Res 5%; Artikkelnr Noca: 27049000; Assembly: Not mounted
U5-U7 = TMUX1511: Low-Capacitance, 1:1 (SPST) 4-Channel, analog switch; Manufacturer: Texas Instruments; Manufacturer Part Number: TMUX1511RSVR; Part number NEMS: 101900847; Component Status: Active; Pad Count: 16; Note: N.A.
U8 U12-U14 = TXB0104RUTR: 4-Bit Bidirectional Level-Shifter/Voltage Translator with Automatic Direction Sensing; Manufacturer: Texas Instruments; Part number NEMS: 101900856; Component Status: Active; Pad Count: 12; Note: Translator, Bidirectional; Artikkelnr Noca: N.A.

## Sheet pca10184_switches.SchDoc: =BoardTitle+' - QSPI Switching'
size A3; Organization: Nordic Semiconductor; DocumentNumber: 7; Revision: 0.3.4; SheetNumber: 7; SheetTotal: 9; Author: GETR; CompanyName: Nordic Semiconductor; DrawnBy: GETR; DocumentSize: A4
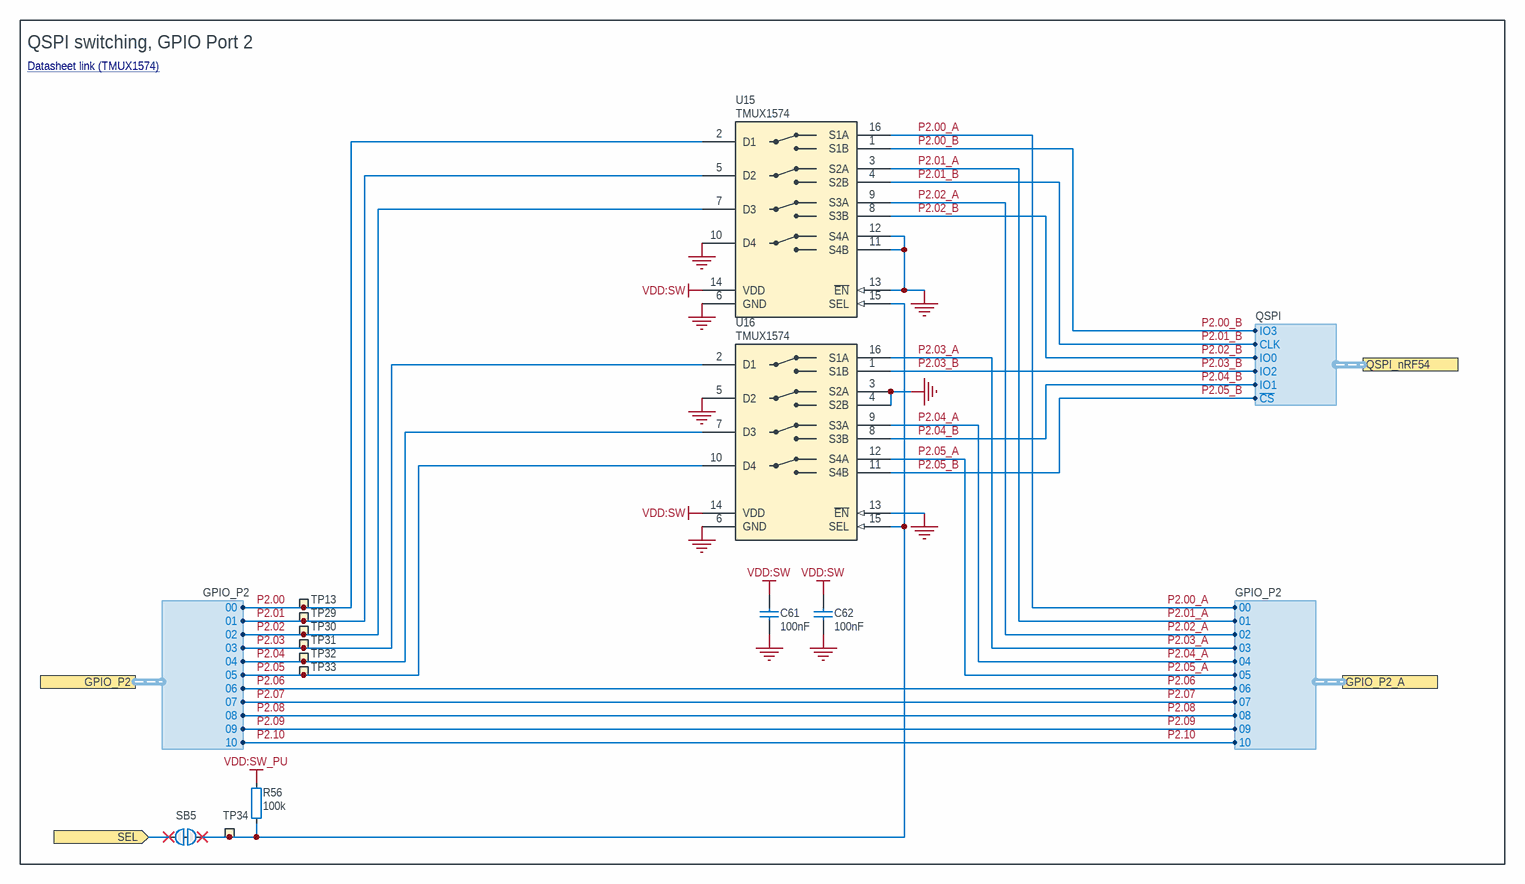
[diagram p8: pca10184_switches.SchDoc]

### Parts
C61  100nF  [CAPC0603X03L_C]
C62  100nF  [CAPC0603X03L_C]
R56  100k  [RESC0603X03L_C]
SB5  Solderbridge  [Solderbridge_Shorted]  (value not drawn)  (net tie, no BOM)
TP13  Ø0.7mm,SMD  [TP_SMD_D0.7mm]  (value not drawn)  (no BOM)
TP29  Ø0.7mm,SMD  [TP_SMD_D0.7mm]  (value not drawn)  (no BOM)
TP30  Ø0.7mm,SMD  [TP_SMD_D0.7mm]  (value not drawn)  (no BOM)
TP31  Ø0.7mm,SMD  [TP_SMD_D0.7mm]  (value not drawn)  (no BOM)
TP32  Ø0.7mm,SMD  [TP_SMD_D0.7mm]  (value not drawn)  (no BOM)
TP33  Ø0.7mm,SMD  [TP_SMD_D0.7mm]  (value not drawn)  (no BOM)
TP34  Ø0.7mm,SMD  [TP_SMD_D0.7mm]  (value not drawn)  (no BOM)
U15  TMUX1574  [XQFN40P180X260X50-16N]
U16  TMUX1574  [XQFN40P180X260X50-16N]

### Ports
GPIO_P2 (harness GPIO_P2), GPIO_P2_A (harness GPIO_P2), QSPI_nRF54 (harness QSPI), SEL (in)

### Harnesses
GPIO_P2: 00, 01, 02, 03, 04, 05, 06, 07, 08, 09, 10
QSPI: ~{CS}, IO0, CLK, IO1, IO2, IO3

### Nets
GND: C61.2 C62.2 U15.6(GND) U15.10(D4) U15.11(S4B) U15.12(S4A) U15.13(~{EN}) U16.3(S2A) U16.4(S2B) U16.5(D2) U16.6(GND) U16.13(~{EN})
VDD:SW: C61.1 C62.1 U15.14(VDD) U16.14(VDD)
VDD:SW_PU: R56.2
P2.00: TP13.1 U15.2(D1) ; port GPIO_P2.00
P2.00_A: U15.16(S1A) ; port GPIO_P2_A.00
P2.00_B: U15.1(S1B) ; port QSPI_nRF54.IO3
P2.01: TP29.1 U15.5(D2) ; port GPIO_P2.01
P2.01_A: U15.3(S2A) ; port GPIO_P2_A.01
P2.01_B: U15.4(S2B) ; port QSPI_nRF54.CLK
P2.02: TP30.1 U15.7(D3) ; port GPIO_P2.02
P2.02_A: U15.9(S3A) ; port GPIO_P2_A.02
P2.02_B: U15.8(S3B) ; port QSPI_nRF54.IO0
P2.03: TP31.1 U16.2(D1) ; port GPIO_P2.03
P2.03_A: U16.16(S1A) ; port GPIO_P2_A.03
P2.03_B: U16.1(S1B) ; port QSPI_nRF54.IO2
P2.04: TP32.1 U16.7(D3) ; port GPIO_P2.04
P2.04_A: U16.9(S3A) ; port GPIO_P2_A.04
P2.04_B: U16.8(S3B) ; port QSPI_nRF54.IO1
P2.05: TP33.1 U16.10(D4) ; port GPIO_P2.05
P2.05_A: U16.12(S4A) ; port GPIO_P2_A.05
P2.05_B: U16.11(S4B) ; port QSPI_nRF54.~{CS}
P2.06: port GPIO_P2.06, port GPIO_P2_A.06
P2.07: port GPIO_P2.07, port GPIO_P2_A.07
P2.08: port GPIO_P2.08, port GPIO_P2_A.08
P2.09: port GPIO_P2.09, port GPIO_P2_A.09
P2.10: port GPIO_P2.10, port GPIO_P2_A.10
QSPI_CTRL: SB5.1 ; port SEL
NetR56_1: R56.1 SB5.2 TP34.1 U15.15(SEL) U16.15(SEL)

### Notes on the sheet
- QSPI switching, GPIO Port 2
- Datasheet link (TMUX1574) <https://www.ti.com/lit/ds/symlink/tmux1574.pdf?ts=1730869182960>

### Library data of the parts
C61 C62 = C0201-100n: as C78-C86 on sheet pca10184_level_shifters
R56 = R0201-100k: as R35 on sheet pca10184_misc
SB5 = Solderbridge Shorted: as SB23 on sheet pca10184_misc
TP13 TP29-TP34 = TP_SMD_Ø0.7MM: 0.7mm circular SMD testpad; Manufacturer: Nordic Semiconductor; Manufacturer Part Number: N.A.; Part number NEMS: 100500474; Component Status: Active; Pad Count: 1
U15 U16 = TMUX1574: Low-Capacitance, 2:1 (SPDT) 4-Channel, analog switch; Manufacturer: Texas Instruments; Manufacturer Part Number: TMUX1574RSVR; Part number NEMS: 101900850; Component Status: Active; Pad Count: 16; Note: N.A.

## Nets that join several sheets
5V0:CONN: pca10184_power_supply (SB31.1), pca10184_connectors (6 pins)
GND: pca10184_debugger_mcu (33 pins), pca10184_power_supply (42 pins), pca10184_nrf54lm20 (31 pins), pca10184_connectors (56 pins), pca10184_misc (18 pins), pca10184_level_shifters (22 pins), pca10184_switches (12 pins)
P5V0: pca10184_debugger_mcu (FB5.2), pca10184_power_supply (8 pins)
P5V0:LED: pca10184_power_supply (C52.2 TP1.1 U3.31), pca10184_misc (R25.2 R26.2 R27.2 R28.2)
VBUS: pca10184_debugger_mcu (J2.5), pca10184_power_supply (10 pins)
VBUS:DBGR: pca10184_debugger_mcu (R5.2), pca10184_power_supply (Q2.1 R20.1 R21.1), pca10184_connectors (C69.2 FB4.2)
VBUS:nRF: pca10184_power_supply (SB6.2), pca10184_nrf54lm20 (R1.2), pca10184_connectors (C63.2 FB3.2)
VDD:DBGR: pca10184_debugger_mcu (29 pins), pca10184_misc (R35.2), pca10184_level_shifters (10 pins)
VDD:IO: pca10184_power_supply (6 pins), pca10184_connectors (14 pins), pca10184_misc (SB23.1), pca10184_level_shifters (7 pins)
VDD:nRF: pca10184_power_supply (P14.2 R15.1 R55.1 SB19.2), pca10184_nrf54lm20 (9 pins), pca10184_misc (SB24.1), pca10184_level_shifters (R43.1)
VDD:SW: pca10184_level_shifters (10 pins), pca10184_switches (C61.1 C62.1 U15.14 U16.14)
VDD:SW_PU: pca10184_level_shifters (7 pins), pca10184_switches (R56.2)
VDD:SWD0: pca10184_connectors (P13.1), pca10184_level_shifters (C89.1 R41.2 U8.11)
DBGR_BUTTON: pca10184_top_level (SB26.2), pca10184_debugger_mcu (U2.AL27)
DBGR_N: pca10184_debugger_mcu (U2.B4), pca10184_connectors (U11.7)
DBGR_P: pca10184_debugger_mcu (U2.B2), pca10184_connectors (U11.6)
LED_PWR_CTRL: pca10184_debugger_mcu (U2.A17), pca10184_power_supply (U3.8)
NetJ4_A5: pca10184_power_supply (U3.23), pca10184_connectors (J4.A5)
NetJ4_B5: pca10184_power_supply (U3.24), pca10184_connectors (J4.B5)
NetR6_2: pca10184_debugger_mcu (R6.2), pca10184_level_shifters (U8.2)
NetR12_2: pca10184_debugger_mcu (R12.2), pca10184_level_shifters (U8.3)
NetR13_2: pca10184_debugger_mcu (R13.2), pca10184_level_shifters (U8.4)
NetR47_2: pca10184_debugger_mcu (R47.2), pca10184_level_shifters (U8.5)
NetR48_2: pca10184_debugger_mcu (R48.2), pca10184_level_shifters (U14.2)
NetR49_2: pca10184_debugger_mcu (R49.2), pca10184_level_shifters (U14.3)
NetR50_2: pca10184_debugger_mcu (R50.2), pca10184_level_shifters (U14.4)
NetSB22_1: pca10184_top_level (SB25.2 SB26.1), pca10184_misc (SB22.1 SW6.2)
NFC1_N: pca10184_connectors (J5.2 TP26.1), pca10184_misc (C56.1 R33.2)
NFC2_P: pca10184_connectors (J5.4 TP28.1), pca10184_misc (C57.2 R34.2)
NFC_N: pca10184_nrf54lm20 (R3.2 U1.J6), pca10184_misc (R33.1)
NFC_P: pca10184_nrf54lm20 (R4.2 U1.J7), pca10184_misc (R34.1)
nRF54_RESET: pca10184_top_level (SB25.1), pca10184_nrf54lm20 (U1.F2), pca10184_connectors (P11.10 P12.10), pca10184_level_shifters (U7.9)
P0.00: pca10184_nrf54lm20 (U1.K3), pca10184_connectors (P1.3)
P0.01: pca10184_nrf54lm20 (U1.K2), pca10184_connectors (P1.4)
P0.02: pca10184_nrf54lm20 (U1.J3), pca10184_connectors (P1.5)
P0.03: pca10184_nrf54lm20 (U1.J2), pca10184_connectors (P1.6 P17.11)
P0.04: pca10184_nrf54lm20 (U1.J1), pca10184_connectors (P1.7 P17.12)
P0.05: pca10184_nrf54lm20 (U1.H3), pca10184_connectors (P1.8), pca10184_misc (SW4.2)
P0.06: pca10184_nrf54lm20 (U1.H2), pca10184_connectors (P1.9), pca10184_level_shifters (U5.6)
P0.07: pca10184_nrf54lm20 (U1.G3), pca10184_connectors (P1.10), pca10184_level_shifters (U5.3)
P0.08: pca10184_nrf54lm20 (U1.F3), pca10184_connectors (P1.11), pca10184_level_shifters (U5.13)
P0.09: pca10184_nrf54lm20 (U1.E3), pca10184_connectors (P1.12), pca10184_level_shifters (U5.9)
P1.00: pca10184_nrf54lm20 (U1.K8), pca10184_connectors (P2.3)
P1.01: pca10184_nrf54lm20 (R3.1), pca10184_connectors (P2.4)
P1.02: pca10184_nrf54lm20 (R4.1), pca10184_connectors (P2.5 P17.5)
P1.03: pca10184_nrf54lm20 (U1.H9), pca10184_connectors (P2.6 P17.6)
P1.04: pca10184_nrf54lm20 (U1.J9), pca10184_connectors (P2.7 P17.7)
P1.05: pca10184_nrf54lm20 (U1.H8), pca10184_connectors (P2.8 P17.17)
P1.06: pca10184_nrf54lm20 (U1.J8), pca10184_connectors (P2.9 P17.16)
P1.07: pca10184_nrf54lm20 (U1.G8), pca10184_connectors (P2.10 P17.15)
P1.08: pca10184_nrf54lm20 (U1.F8), pca10184_connectors (P2.11), pca10184_misc (SW3.2)
P1.09: pca10184_nrf54lm20 (U1.E8), pca10184_connectors (P2.12), pca10184_misc (SW2.2)
P1.10: pca10184_nrf54lm20 (U1.D5), pca10184_connectors (P2.13)
P1.11: pca10184_nrf54lm20 (U1.C5), pca10184_connectors (P2.14)
P1.12: pca10184_nrf54lm20 (U1.C4), pca10184_connectors (P2.15)
P1.13: pca10184_nrf54lm20 (U1.C3), pca10184_connectors (P2.16 P17.8)
P1.14: pca10184_nrf54lm20 (U1.C2), pca10184_connectors (P2.17)
P1.15: pca10184_nrf54lm20 (U1.B2), pca10184_connectors (P2.18)
P1.16: pca10184_nrf54lm20 (U1.B3), pca10184_connectors (P3.3), pca10184_level_shifters (U6.6)
P1.17: pca10184_nrf54lm20 (U1.B4), pca10184_connectors (P3.4), pca10184_level_shifters (U6.3)
P1.18: pca10184_nrf54lm20 (U1.B5), pca10184_connectors (P3.5), pca10184_level_shifters (U6.13)
P1.19: pca10184_nrf54lm20 (U1.B6), pca10184_connectors (P3.6), pca10184_level_shifters (U6.9)
P1.20: pca10184_nrf54lm20 (SB3.2), pca10184_connectors (P3.7)
P1.21: pca10184_nrf54lm20 (SB4.2), pca10184_connectors (P3.8)
P1.22: pca10184_nrf54lm20 (U1.D6), pca10184_connectors (P3.9), pca10184_misc (Q4.1 R32.1)
P1.23: pca10184_nrf54lm20 (U1.B7), pca10184_connectors (P3.10)
P1.24: pca10184_nrf54lm20 (U1.D7), pca10184_connectors (P3.11)
P1.25: pca10184_nrf54lm20 (U1.E7), pca10184_connectors (P3.12), pca10184_misc (Q5.1 R29.1)
P1.26: pca10184_nrf54lm20 (U1.B8), pca10184_connectors (P3.13), pca10184_misc (SW1.2)
P1.27: pca10184_nrf54lm20 (U1.C8), pca10184_connectors (P3.14), pca10184_misc (Q6.1 R30.1)
P1.28: pca10184_nrf54lm20 (U1.D8), pca10184_connectors (P3.15), pca10184_misc (Q7.1 R31.1)
P1.29: pca10184_nrf54lm20 (U1.H10), pca10184_connectors (P3.16)
P1.30: pca10184_nrf54lm20 (U1.J10), pca10184_connectors (P3.17)
P1.31: pca10184_nrf54lm20 (U1.K9), pca10184_connectors (P3.18)
P2.00: pca10184_nrf54lm20 (U1.B10), pca10184_switches (TP13.1 U15.2)
P2.00_A: pca10184_connectors (P4.3 P17.21), pca10184_switches (U15.16)
P2.00_B: pca10184_misc (U4.7), pca10184_switches (U15.1)
P2.01: pca10184_nrf54lm20 (U1.C10), pca10184_switches (TP29.1 U15.5)
P2.01_A: pca10184_connectors (P4.4 P17.22), pca10184_switches (U15.3)
P2.01_B: pca10184_misc (U4.6), pca10184_switches (U15.4)
P2.02: pca10184_nrf54lm20 (U1.D10), pca10184_switches (TP30.1 U15.7)
P2.02_A: pca10184_connectors (P4.5 P17.23), pca10184_switches (U15.9)
P2.02_B: pca10184_misc (U4.5), pca10184_switches (U15.8)
P2.03: pca10184_nrf54lm20 (U1.E10), pca10184_switches (TP31.1 U16.2)
P2.03_A: pca10184_connectors (P4.6 P17.24), pca10184_switches (U16.16)
P2.03_B: pca10184_misc (U4.3), pca10184_switches (U16.1)
P2.04: pca10184_nrf54lm20 (U1.F10), pca10184_switches (TP32.1 U16.7)
P2.04_A: pca10184_connectors (P4.7 P17.25), pca10184_switches (U16.9)
P2.04_B: pca10184_misc (U4.2), pca10184_switches (U16.8)
P2.05: pca10184_nrf54lm20 (U1.G9), pca10184_switches (TP33.1 U16.10)
P2.05_A: pca10184_connectors (P4.8 P17.26), pca10184_switches (U16.12)
P2.05_B: pca10184_misc (U4.1), pca10184_switches (U16.11)
P2.06: pca10184_nrf54lm20 (U1.B9), pca10184_connectors (P4.9 P12.12)
P2.07: pca10184_nrf54lm20 (U1.C9), pca10184_connectors (P4.10 P11.6 P12.6 P12.14)
P2.08: pca10184_nrf54lm20 (U1.D9), pca10184_connectors (P4.11 P12.16)
P2.09: pca10184_nrf54lm20 (U1.E9), pca10184_connectors (P4.12 P12.18)
P2.10: pca10184_nrf54lm20 (U1.F9), pca10184_connectors (P4.13 P12.20)
P3.00: pca10184_nrf54lm20 (U1.H7), pca10184_connectors (P5.3 P17.9)
P3.01: pca10184_nrf54lm20 (U1.H6), pca10184_connectors (P5.4 P17.10)
P3.02: pca10184_nrf54lm20 (U1.H5), pca10184_connectors (P5.5 P17.13)
P3.03: pca10184_nrf54lm20 (U1.H4), pca10184_connectors (P5.6 P17.14)
P3.04: pca10184_nrf54lm20 (U1.J4), pca10184_connectors (P5.7 P17.4)
P3.05: pca10184_nrf54lm20 (U1.G7), pca10184_connectors (P5.8 P17.3)
P3.06: pca10184_nrf54lm20 (U1.G6), pca10184_connectors (P5.9 P17.18)
P3.07: pca10184_nrf54lm20 (U1.G5), pca10184_connectors (P5.10)
P3.08: pca10184_nrf54lm20 (U1.G4), pca10184_connectors (P5.11)
P3.09: pca10184_nrf54lm20 (U1.F7), pca10184_connectors (P5.12)
P3.10: pca10184_nrf54lm20 (U1.F4), pca10184_connectors (P5.13)
P3.11: pca10184_nrf54lm20 (U1.E4), pca10184_connectors (P5.14)
P3.12: pca10184_nrf54lm20 (U1.D4), pca10184_connectors (P5.15)
QSPI_CTRL: pca10184_debugger_mcu (U2.B14), pca10184_switches (SB5.1)
SWD0_CLK_EXT: pca10184_connectors (P13.6), pca10184_level_shifters (U8.8)
SWD0_IO_EXT: pca10184_connectors (P13.10), pca10184_level_shifters (U8.7)
SWD0_RESET_EXT: pca10184_connectors (P13.2), pca10184_level_shifters (U8.10)
SWD0_SEL: pca10184_debugger_mcu (U2.B24), pca10184_connectors (P13.3), pca10184_level_shifters (Q9.1)
SWD0_SWO_EXT: pca10184_connectors (P13.4), pca10184_level_shifters (U8.9)
SWD3_CTRL: pca10184_debugger_mcu (U2.AB2), pca10184_level_shifters (R40.2 U7.1 U7.4 U7.11)
SWDCLK: pca10184_nrf54lm20 (U1.G1), pca10184_connectors (P11.4 P12.4), pca10184_level_shifters (U7.6)
SWDIO: pca10184_nrf54lm20 (U1.G2), pca10184_connectors (P11.2 P12.2), pca10184_level_shifters (U7.3)
TWI0_SCL: pca10184_debugger_mcu (U2.AF2), pca10184_power_supply (U3.14)
TWI0_SDA: pca10184_debugger_mcu (U2.AE1), pca10184_power_supply (U3.13)
UART0_CTRL: pca10184_debugger_mcu (U2.R31), pca10184_level_shifters (R36.2 U5.1 U5.4 U12.12)
UART0_CTS_DBGR: pca10184_debugger_mcu (R9.1 U2.AL9), pca10184_level_shifters (U12.5)
UART0_HWFC: pca10184_debugger_mcu (U2.AK16), pca10184_level_shifters (R19.2 U5.11 U5.15)
UART0_RTS_DBGR: pca10184_debugger_mcu (U2.AL5), pca10184_level_shifters (U12.4)
UART0_RxD_DBGR: pca10184_debugger_mcu (U2.AL19), pca10184_level_shifters (U12.3)
UART0_TxD_DBGR: pca10184_debugger_mcu (U2.U31), pca10184_level_shifters (U12.2)
UART1_CTRL: pca10184_debugger_mcu (U2.AK18), pca10184_level_shifters (R38.2 U6.1 U6.4 U13.12)
UART1_CTS_DBGR: pca10184_debugger_mcu (R10.1 U2.AL15), pca10184_level_shifters (U13.5)
UART1_HWFC: pca10184_debugger_mcu (U2.AK20), pca10184_level_shifters (R37.2 U6.11 U6.15)
UART1_RTS_DBGR: pca10184_debugger_mcu (U2.AL13), pca10184_level_shifters (U13.4)
UART1_RxD_DBGR: pca10184_debugger_mcu (U2.AL21), pca10184_level_shifters (U13.3)
UART1_TxD_DBGR: pca10184_debugger_mcu (U2.AL23), pca10184_level_shifters (U13.2)
USB_nRF54_D+: pca10184_nrf54lm20 (U1.K5), pca10184_connectors (U10.6)
USB_nRF54_D-: pca10184_nrf54lm20 (U1.K4), pca10184_connectors (U10.7)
